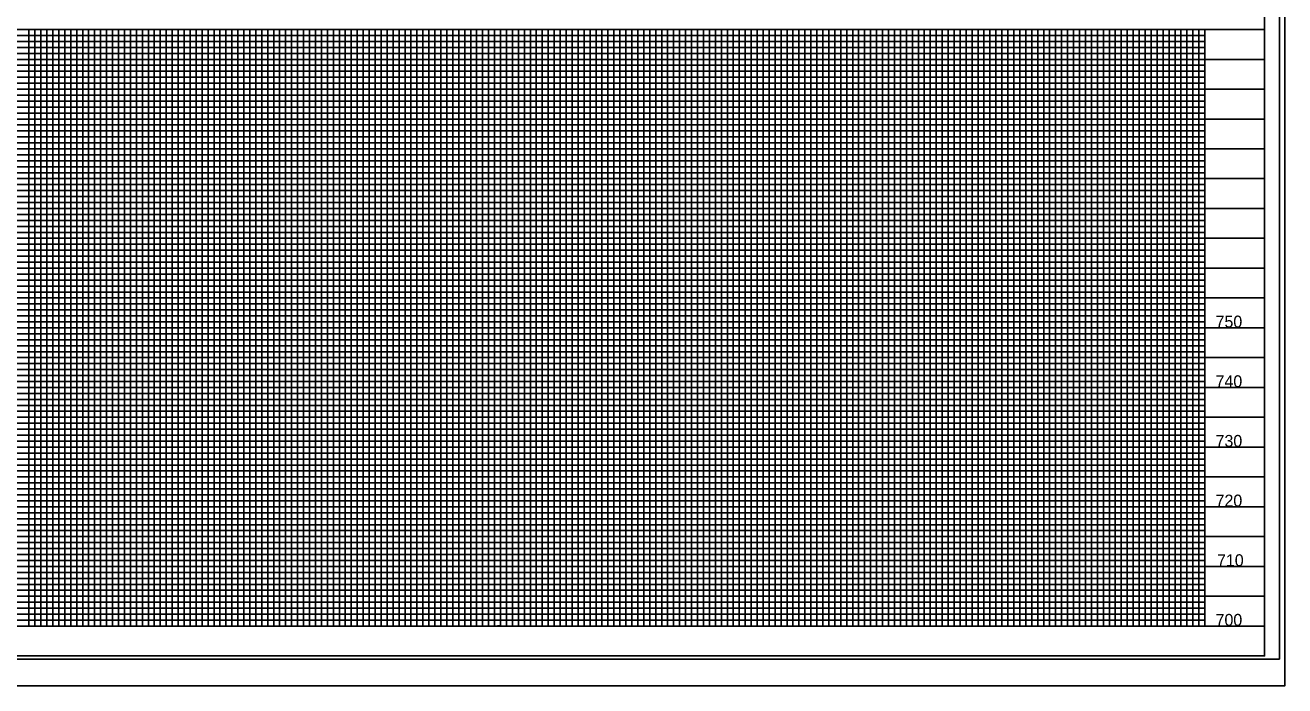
# Model space of a CAD drawing. Extents: x 573926 to 575610, y -51565 to -50465.
# Drawn here: x 574555 to 575610, y -51565 to -51011 of the extents above; entities that cross this region are included whole.
import ezdxf

# ---------------------------------------------------------------- set-up
doc = ezdxf.new("R2010")
doc.units = 0
for name, color, linetype in [('Exist Vertical Profile Vertical Axis Label', 7, 'Continuous'), ('Sheet Cutting Line CELL', 7, 'Continuous'), ('Sheet DOT Grid CELL', 7, 'Continuous'), ('Sheet Layout Profile Border Port 2', 7, 'Continuous'), ('Sheet Plot Border Inside CELL', 7, 'Continuous'), ('Sheet Plot Border Outside CELL', 7, 'Continuous'), ('Sheet Profile CELL', 7, 'Continuous'), ('Sheet Profile Grid Major CELL', 7, 'Continuous'), ('Sheet Profile Grid Middle CELL', 7, 'Continuous'), ('Sheet Profile Grid Minor CELL', 7, 'Continuous')]:
    doc.layers.add(name, color=color, linetype=linetype)

msp = doc.modelspace()

# ---------------------------------------------------------------- linework, layer by layer
at = {"layer": 'Sheet Cutting Line CELL'}
msp.add_line((573925.8, -51564.9), (575609.8, -51564.9), dxfattribs=at)
at = {"layer": 'Sheet DOT Grid CELL'}
for p, q in [((574092.8, -51014.9), (575592.7, -51014.9)), ((574592.8, -51014.9), (574592.8, -51514.9)), ((574642.8, -51014.9), (574642.8, -51514.9)), ((574692.8, -51014.9), (574692.8, -51514.9)), ((574742.8, -51014.9), (574742.8, -51514.9)), ((574792.8, -51014.9), (574792.8, -51514.9)), ((574842.8, -51014.9), (574842.8, -51514.9)), ((574892.8, -51014.9), (574892.8, -51514.9)), ((574942.8, -51014.9), (574942.8, -51514.9)), ((574992.8, -51014.9), (574992.8, -51514.9)), ((575042.8, -51014.9), (575042.8, -51514.9)), ((575092.8, -51014.9), (575092.8, -51514.9)), ((575142.8, -51014.9), (575142.8, -51514.9)), ((575192.8, -51014.9), (575192.8, -51514.9)), ((575242.8, -51014.9), (575242.8, -51514.9)), ((575292.8, -51014.9), (575292.8, -51514.9)), ((575342.8, -51014.9), (575342.8, -51514.9)), ((575392.8, -51014.9), (575392.8, -51514.9)), ((575442.8, -51014.9), (575442.8, -51514.9)), ((575492.8, -51014.9), (575492.8, -51514.9)), ((575542.8, -51014.9), (575542.8, -51514.9)), ((574092.8, -51064.9), (575592.7, -51064.9)), ((574092.8, -51114.9), (575592.7, -51114.9)), ((574092.8, -51164.9), (575592.7, -51164.9)), ((574092.8, -51214.9), (575592.7, -51214.9)), ((574092.8, -51264.9), (575592.7, -51264.9)), ((574092.8, -51314.9), (575592.7, -51314.9)), ((574092.8, -51364.9), (575592.7, -51364.9)), ((574092.8, -51414.9), (575592.7, -51414.9)), ((574092.8, -51464.9), (575592.7, -51464.9))]:
    msp.add_line(p, q, dxfattribs=at)
at = {"layer": 'Sheet Layout Profile Border Port 2'}
msp.add_lwpolyline([(574142.8, -51014.9), (575542.8, -51014.9), (575542.8, -51514.9), (574142.8, -51514.9)], close=True, dxfattribs=at)
at = {"layer": 'Sheet Plot Border Inside CELL'}
msp.add_lwpolyline([(573938.8, -51542.5), (575605.3, -51542.5), (575605.3, -50487.4), (573938.8, -50487.4)], close=True, dxfattribs=at)
at = {"layer": 'Sheet Plot Border Outside CELL'}
msp.add_lwpolyline([(573925.8, -51564.9), (575609.8, -51564.9), (575609.8, -50464.9), (573925.8, -50464.9)], close=True, dxfattribs=at)
at = {"layer": 'Sheet Profile CELL'}
for p, q in [((574092.8, -51014.9), (575592.8, -51014.9)), ((575592.8, -51514.9), (574092.8, -51514.9)), ((574092.8, -51539.9), (575592.8, -51539.9))]:
    msp.add_line(p, q, dxfattribs=at)
msp.add_lwpolyline([(575592.8, -50489.9), (574092.8, -50489.9), (574092.8, -51539.9), (575592.8, -51539.9)], close=True, dxfattribs=at)
at = {"layer": 'Sheet Profile Grid Major CELL'}
for p, q in [((574592.8, -51014.9), (574642.8, -51014.9)), ((574692.8, -51014.9), (574742.8, -51014.9)), ((574792.8, -51014.9), (574842.8, -51014.9)), ((574892.8, -51014.9), (574942.8, -51014.9)), ((574992.8, -51014.9), (575042.8, -51014.9)), ((575092.8, -51014.9), (575142.8, -51014.9)), ((575192.8, -51014.9), (575242.8, -51014.9)), ((575292.8, -51014.9), (575342.8, -51014.9)), ((575392.8, -51014.9), (575442.8, -51014.9)), ((575492.8, -51014.9), (575542.8, -51014.9)), ((575492.8, -51514.9), (575492.8, -51514.9))]:
    msp.add_line(p, q, dxfattribs=at)
for points in [[(574542.8, -51514.9), (574592.8, -51514.9), (574592.8, -51014.9), (574642.8, -51014.9), (574642.8, -51514.9), (574692.8, -51514.9), (574692.8, -51014.9), (574742.8, -51014.9), (574742.8, -51514.9), (574792.8, -51514.9), (574792.8, -51014.9), (574842.8, -51014.9), (574842.8, -51514.9), (574892.8, -51514.9), (574892.8, -51014.9), (574942.8, -51014.9), (574942.8, -51514.9), (574992.8, -51514.9), (574992.8, -51014.9), (575042.8, -51014.9), (575042.8, -51514.9), (575092.8, -51514.9), (575092.8, -51014.9), (575142.8, -51014.9), (575142.8, -51514.9), (575192.8, -51514.9), (575192.8, -51014.9), (575242.8, -51014.9), (575242.8, -51514.9), (575292.8, -51514.9), (575292.8, -51014.9), (575342.8, -51014.9), (575342.8, -51514.9), (575392.8, -51514.9), (575392.8, -51014.9), (575442.8, -51014.9), (575442.8, -51514.9), (575492.8, -51514.9), (575492.8, -51514.9), (575492.8, -51014.9), (575542.8, -51014.9), (575542.8, -51514.9)], [(575592.8, -51064.9), (574092.8, -51064.9)], [(575592.8, -51114.9), (574092.8, -51114.9), (574092.8, -51164.9), (575592.8, -51164.9)], [(575592.8, -51214.9), (574092.8, -51214.9), (574092.8, -51264.9), (575592.8, -51264.9)], [(575592.8, -51314.9), (574092.8, -51314.9), (574092.8, -51364.9), (575592.8, -51364.9)], [(575592.8, -51414.9), (574092.8, -51414.9), (574092.8, -51414.9), (574092.8, -51464.9), (575592.8, -51464.9)], [(575592.8, -51514.9), (574092.8, -51514.9)]]:
    msp.add_lwpolyline(points, dxfattribs=at)
at = {"layer": 'Sheet Profile Grid Middle CELL'}
for points in [[(574517.8, -51014.9), (574567.8, -51014.9), (574567.8, -51514.9), (574617.8, -51514.9), (574617.8, -51014.9), (574667.8, -51014.9), (574667.8, -51514.9), (574717.8, -51514.9), (574717.8, -51514.9), (574717.8, -51014.9), (574767.8, -51014.9), (574767.8, -51514.9), (574817.8, -51514.9), (574817.8, -51014.9), (574867.8, -51014.9), (574867.8, -51514.9), (574917.8, -51514.9), (574917.8, -51014.9), (574967.8, -51014.9), (574967.8, -51514.9), (575017.8, -51514.9), (575017.8, -51014.9), (575067.8, -51014.9), (575067.8, -51514.9), (575117.8, -51514.9), (575117.8, -51014.9), (575167.8, -51014.9), (575167.8, -51514.9), (575217.8, -51514.9), (575217.8, -51014.9), (575267.8, -51014.9), (575267.8, -51514.9), (575317.8, -51514.9), (575317.8, -51014.9), (575367.8, -51014.9), (575367.8, -51514.9), (575417.8, -51514.9), (575417.8, -51014.9), (575467.8, -51014.9), (575467.8, -51514.9), (575517.8, -51514.9), (575517.8, -51014.9)], [(574092.8, -51039.9), (575592.8, -51039.9)], [(575592.8, -51089.9), (574092.8, -51089.9), (574092.8, -51139.9), (575592.8, -51139.9)], [(575592.8, -51189.9), (574092.8, -51189.9), (574092.8, -51239.9), (575592.8, -51239.9)], [(575592.8, -51289.9), (574092.8, -51289.9), (574092.8, -51339.9), (575592.8, -51339.9)], [(575592.8, -51389.9), (574092.8, -51389.9), (574092.8, -51439.9), (575592.8, -51439.9)], [(575592.8, -51489.9), (574092.8, -51489.9)]]:
    msp.add_lwpolyline(points, dxfattribs=at)
at = {"layer": 'Sheet Profile Grid Minor CELL'}
for p, q in [((574142.8, -51019.9), (575542.8, -51019.9)), ((575542.8, -51024.9), (574142.8, -51024.9)), ((574142.8, -51029.9), (575542.8, -51029.9)), ((575542.8, -51034.9), (574142.8, -51034.9)), ((574142.8, -51044.9), (575542.8, -51044.9)), ((575542.8, -51049.9), (574142.8, -51049.9)), ((574142.8, -51054.9), (575542.8, -51054.9)), ((575542.8, -51059.9), (574142.8, -51059.9)), ((574142.8, -51069.9), (575542.8, -51069.9)), ((575542.8, -51074.9), (574142.8, -51074.9)), ((574142.8, -51079.9), (575542.8, -51079.9)), ((575542.8, -51084.9), (574142.8, -51084.9)), ((574142.8, -51094.9), (575542.8, -51094.9)), ((575542.8, -51099.9), (574142.8, -51099.9)), ((574142.8, -51104.9), (575542.8, -51104.9)), ((575542.8, -51109.9), (574142.8, -51109.9)), ((574142.8, -51119.9), (575542.8, -51119.9)), ((575542.8, -51124.9), (574142.8, -51124.9)), ((574142.8, -51129.9), (575542.8, -51129.9)), ((575542.8, -51134.9), (574142.8, -51134.9)), ((574142.8, -51144.9), (575542.8, -51144.9)), ((575542.8, -51149.9), (574142.8, -51149.9)), ((574142.8, -51154.9), (575542.8, -51154.9)), ((575542.8, -51159.9), (574142.8, -51159.9)), ((574142.8, -51169.9), (575542.8, -51169.9)), ((575542.8, -51174.9), (574142.8, -51174.9)), ((574142.8, -51179.9), (575542.8, -51179.9)), ((575542.8, -51184.9), (574142.8, -51184.9)), ((574142.8, -51194.9), (575542.8, -51194.9)), ((575542.8, -51199.9), (574142.8, -51199.9)), ((574142.8, -51204.9), (575542.8, -51204.9)), ((575542.8, -51209.9), (574142.8, -51209.8)), ((574142.8, -51219.9), (575542.8, -51219.9)), ((575542.8, -51224.9), (574142.8, -51224.9)), ((574142.8, -51229.9), (575542.8, -51229.9)), ((575542.8, -51234.9), (574142.8, -51234.9)), ((574142.8, -51244.9), (575542.8, -51244.9)), ((575542.8, -51249.9), (574142.8, -51249.9)), ((574142.8, -51254.9), (575542.8, -51254.9)), ((575542.8, -51259.9), (574142.8, -51259.9)), ((574142.8, -51269.9), (575542.8, -51269.9)), ((575542.8, -51274.9), (574142.8, -51274.9)), ((574142.8, -51279.9), (575542.8, -51279.9)), ((575542.8, -51284.9), (574142.8, -51284.9)), ((574142.8, -51294.9), (575542.8, -51294.9)), ((575542.8, -51299.9), (574142.8, -51299.9)), ((574142.8, -51304.9), (575542.8, -51304.9)), ((575542.8, -51309.9), (574142.8, -51309.9)), ((574142.8, -51319.9), (575542.8, -51319.9)), ((575542.8, -51324.9), (574142.8, -51324.9)), ((574142.8, -51329.9), (575542.8, -51329.9)), ((575542.8, -51334.9), (574142.8, -51334.9)), ((574142.8, -51344.9), (575542.8, -51344.9)), ((575542.8, -51349.9), (574142.8, -51349.9)), ((574142.8, -51354.9), (575542.8, -51354.9)), ((575542.8, -51359.9), (574142.8, -51359.9)), ((574142.8, -51369.9), (575542.8, -51369.9)), ((575542.8, -51374.9), (574142.8, -51374.9)), ((574142.8, -51379.9), (575542.8, -51379.9)), ((575542.8, -51384.9), (574142.8, -51384.9)), ((574142.8, -51394.9), (575542.8, -51394.9)), ((575542.8, -51399.9), (574142.8, -51399.9)), ((574142.8, -51404.9), (575542.8, -51404.9)), ((575542.8, -51409.9), (574142.8, -51409.9)), ((574142.8, -51419.9), (575542.8, -51419.9)), ((575542.8, -51424.9), (574142.8, -51424.9)), ((574142.8, -51429.9), (575542.8, -51429.9)), ((575542.8, -51434.9), (574142.8, -51434.9)), ((574142.8, -51444.9), (575542.8, -51444.9)), ((575542.8, -51449.9), (574142.8, -51449.9)), ((574142.8, -51454.9), (575542.8, -51454.9)), ((575542.8, -51459.9), (574142.8, -51459.9)), ((574142.8, -51469.9), (575542.8, -51469.9)), ((575542.8, -51474.9), (574142.8, -51474.9)), ((574142.8, -51479.9), (575542.8, -51479.9)), ((575542.8, -51484.9), (574142.8, -51484.9)), ((574142.8, -51494.9), (575542.8, -51494.9)), ((575542.8, -51499.9), (574142.8, -51499.9)), ((574142.8, -51504.9), (575542.8, -51504.9)), ((574142.8, -51509.9), (575542.8, -51509.9)), ((575542.8, -51509.9), (575542.8, -51509.9))]:
    msp.add_line(p, q, dxfattribs=at)
for points in [[(574552.8, -51014.9), (574557.8, -51014.9), (574557.8, -51514.9), (574562.8, -51514.9), (574562.8, -51014.9), (574572.8, -51014.9), (574572.8, -51514.9), (574577.8, -51514.9), (574577.8, -51014.9), (574582.8, -51014.9), (574582.8, -51514.9), (574587.8, -51514.9), (574587.8, -51014.9), (574597.8, -51014.9), (574597.8, -51514.9), (574602.8, -51514.9), (574602.8, -51014.9), (574607.8, -51014.9), (574607.8, -51514.9), (574612.8, -51514.9), (574612.8, -51014.9), (574622.8, -51014.9), (574622.8, -51514.9), (574627.8, -51514.9), (574627.8, -51014.9), (574632.8, -51014.9), (574632.8, -51514.9), (574637.8, -51514.9), (574637.8, -51014.9), (574647.8, -51014.9), (574647.8, -51514.9), (574652.8, -51514.9), (574652.8, -51014.9), (574657.8, -51014.9), (574657.8, -51514.9), (574662.8, -51514.9), (574662.8, -51014.9), (574672.8, -51014.9)], [(574672.8, -51014.9), (574672.8, -51514.9), (574677.8, -51514.9), (574677.8, -51014.9), (574682.8, -51014.9), (574682.8, -51514.9), (574687.8, -51514.9), (574687.8, -51014.9), (574697.8, -51014.9), (574697.8, -51514.9), (574702.8, -51514.9), (574702.8, -51014.9), (574707.8, -51014.9), (574707.8, -51514.9), (574712.8, -51514.9), (574712.8, -51014.9), (574722.8, -51014.9), (574722.8, -51514.9), (574727.8, -51514.9), (574727.8, -51014.9), (574732.8, -51014.9), (574732.8, -51514.9), (574737.8, -51514.9), (574737.8, -51014.9), (574747.8, -51014.9), (574747.8, -51514.9), (574752.8, -51514.9), (574752.8, -51014.9), (574757.8, -51014.9), (574757.8, -51514.9), (574762.8, -51514.9), (574762.8, -51014.9), (574772.8, -51014.9), (574772.8, -51514.9), (574777.8, -51514.9), (574777.8, -51014.9), (574782.8, -51014.9), (574782.8, -51514.9), (574787.8, -51514.9), (574787.8, -51014.9), (574797.8, -51014.9), (574797.8, -51514.9), (574797.8, -51514.9), (574802.8, -51514.9), (574802.8, -51014.9), (574807.8, -51014.9), (574807.8, -51514.9), (574812.8, -51514.9), (574812.8, -51014.9), (574822.8, -51014.9), (574822.8, -51514.9), (574827.8, -51514.9), (574827.8, -51014.9), (574832.8, -51014.9), (574832.8, -51514.9), (574837.8, -51514.9), (574837.8, -51014.9), (574847.8, -51014.9), (574847.8, -51514.9), (574852.8, -51514.9), (574852.8, -51014.9), (574857.8, -51014.9), (574857.8, -51514.9), (574862.8, -51514.9), (574862.8, -51014.9), (574872.8, -51014.9), (574872.8, -51514.9), (574877.8, -51514.9), (574877.8, -51014.9), (574882.8, -51014.9), (574882.8, -51514.9), (574887.8, -51514.9), (574887.8, -51014.9), (574897.8, -51014.9), (574897.8, -51514.9), (574902.8, -51514.9), (574902.8, -51014.9), (574907.8, -51014.9), (574907.8, -51514.9), (574912.8, -51514.9), (574912.8, -51014.9), (574922.8, -51014.9), (574922.8, -51514.9), (574927.8, -51514.9), (574927.8, -51014.9), (574932.8, -51014.9), (574932.8, -51514.9), (574937.8, -51514.9), (574937.8, -51014.9), (574947.8, -51014.9), (574947.8, -51514.9), (574952.5, -51514.4), (574952.8, -51514.9), (574952.8, -51014.9), (574957.8, -51014.9), (574957.8, -51514.9), (574962.8, -51514.9), (574962.8, -51014.9), (574972.8, -51014.9), (574972.8, -51514.9), (574977.8, -51514.9)], [(574977.8, -51514.9), (574977.8, -51014.9), (574982.8, -51014.9), (574982.8, -51514.9), (574987.8, -51514.9), (574987.8, -51014.9), (574997.8, -51014.9), (574997.8, -51514.9), (575002.8, -51514.9), (575002.8, -51014.9), (575007.8, -51014.9), (575007.8, -51514.9), (575012.8, -51514.9), (575012.8, -51014.9), (575022.8, -51014.9), (575022.8, -51514.9), (575027.8, -51514.9), (575027.8, -51014.9), (575032.8, -51014.9), (575032.8, -51514.9), (575037.8, -51514.9), (575037.8, -51014.9), (575047.8, -51014.9), (575047.8, -51514.9), (575052.8, -51514.9), (575052.8, -51014.9), (575057.8, -51014.9), (575057.8, -51514.9), (575062.8, -51514.9), (575062.8, -51014.9), (575072.8, -51014.9), (575072.8, -51514.9), (575077.8, -51514.9), (575077.8, -51014.9), (575082.8, -51014.9), (575082.8, -51514.9), (575087.8, -51514.9), (575087.8, -51014.9), (575097.8, -51014.9), (575097.8, -51514.9), (575102.8, -51514.9), (575102.8, -51014.9), (575107.8, -51014.9), (575107.8, -51514.9), (575112.8, -51514.9), (575112.8, -51014.9), (575122.8, -51014.9), (575122.8, -51514.9), (575127.8, -51514.9), (575127.8, -51014.9), (575132.8, -51014.9), (575132.8, -51514.9), (575137.8, -51514.9), (575137.8, -51014.9), (575147.8, -51014.9), (575147.8, -51514.9), (575152.8, -51514.9), (575152.8, -51014.9), (575157.8, -51014.9), (575157.8, -51514.9), (575162.8, -51514.9), (575162.8, -51014.9), (575172.8, -51014.9), (575172.8, -51514.9), (575177.8, -51514.9), (575177.8, -51014.9), (575182.8, -51014.9), (575182.8, -51514.9), (575187.8, -51514.9), (575187.8, -51014.9), (575197.8, -51014.9), (575197.8, -51514.9), (575202.8, -51514.9), (575202.8, -51014.9), (575207.8, -51014.9), (575207.8, -51514.9), (575212.8, -51514.9), (575212.8, -51014.9), (575222.8, -51014.9), (575222.8, -51514.9), (575227.8, -51514.9), (575227.8, -51014.9), (575232.8, -51014.9), (575232.8, -51514.9), (575237.8, -51514.9), (575237.8, -51014.9), (575247.8, -51014.9), (575247.8, -51514.9), (575252.8, -51514.9), (575252.8, -51014.9), (575257.8, -51014.9), (575257.8, -51514.9), (575262.8, -51514.9), (575262.8, -51014.9), (575272.8, -51014.9), (575272.8, -51514.9), (575277.8, -51514.9), (575277.8, -51014.9), (575282.8, -51014.9), (575282.8, -51514.9)], [(575282.8, -51514.9), (575287.8, -51514.9), (575287.8, -51014.9), (575297.8, -51014.9), (575297.8, -51514.9), (575302.8, -51514.9), (575302.8, -51014.9), (575307.8, -51014.9), (575307.8, -51514.9), (575312.8, -51514.9), (575312.8, -51014.9), (575322.8, -51014.9), (575322.8, -51514.9), (575327.8, -51514.9), (575327.8, -51014.9), (575332.8, -51014.9), (575332.8, -51514.9), (575337.8, -51514.9), (575337.8, -51014.9), (575347.8, -51014.9), (575347.8, -51514.9), (575352.8, -51514.9), (575352.8, -51014.9), (575357.8, -51014.9), (575357.8, -51514.9), (575362.8, -51514.9), (575362.8, -51014.9), (575372.8, -51014.9), (575372.8, -51514.9), (575377.8, -51514.9), (575377.8, -51014.9), (575382.8, -51014.9), (575382.8, -51514.9), (575387.8, -51514.9), (575387.8, -51014.9), (575397.8, -51014.9), (575397.8, -51514.9), (575402.8, -51514.9), (575402.8, -51014.9), (575407.8, -51014.9), (575407.8, -51514.9), (575412.8, -51514.9), (575412.8, -51014.9), (575422.8, -51014.9), (575422.8, -51514.9), (575427.8, -51514.9), (575427.8, -51014.9), (575432.8, -51014.9), (575432.8, -51514.9), (575437.8, -51514.9), (575437.8, -51014.9), (575447.8, -51014.9), (575447.8, -51514.9), (575452.8, -51514.9), (575452.8, -51014.9), (575457.8, -51014.9), (575457.8, -51514.9), (575462.8, -51514.9), (575462.8, -51014.9), (575472.8, -51014.9), (575472.8, -51514.9), (575477.8, -51514.9), (575477.8, -51014.9), (575482.8, -51014.9), (575482.8, -51514.9), (575487.8, -51514.9), (575487.8, -51014.9), (575497.8, -51014.9), (575497.8, -51514.9), (575502.8, -51514.9), (575502.8, -51014.9), (575507.8, -51014.9), (575507.8, -51514.9), (575512.8, -51514.9), (575512.8, -51014.9), (575522.8, -51014.9), (575522.8, -51514.9), (575527.8, -51514.9), (575527.8, -51014.9), (575532.8, -51014.9), (575532.8, -51514.9), (575537.8, -51514.9), (575537.8, -51014.9), (575542.8, -51014.9)]]:
    msp.add_lwpolyline(points, dxfattribs=at)

# ---------------------------------------------------------------- texts
at = {"layer": 'Exist Vertical Profile Vertical Axis Label'}
for s, p in [('750', (575551.8, -51264.7)), ('740', (575551.8, -51314.7)), ('730', (575551.8, -51364.7)), ('720', (575551.8, -51414.7)), ('710', (575553, -51464.7)), ('700', (575551.8, -51514.7))]:
    msp.add_text(s, height=10, dxfattribs=at).set_placement(p)

doc.saveas('drawing.dxf')
